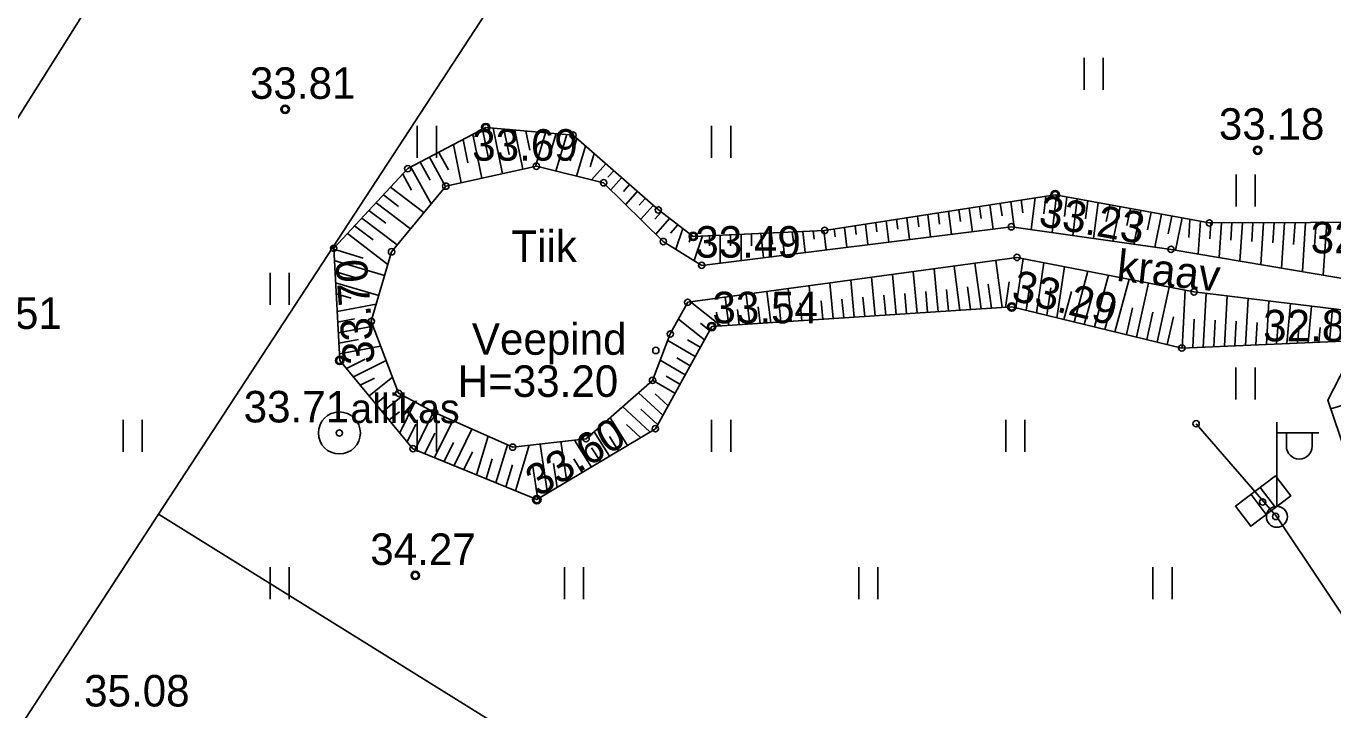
# Model space of a CAD drawing. Extents: x 641898 to 642452, y 6471715 to 6472255.
# Drawn here: x 641996.97 to 642028.05, y 6472175.9 to 6472192.17 of the extents above; entities that cross this region are included whole.
import ezdxf

# ---------------------------------------------------------------- set-up
doc = ezdxf.new("R2010")
doc.units = 0
for name, color, linetype in [('ELRAJATISMP', 7, 'Continuous'), ('HALJASTUS', 7, 'Continuous'), ('KORGUS-EH2000', 7, 'Continuous'), ('MOOTMPUNKT', 7, 'Continuous'), ('MOOTPIIR', 7, 'Continuous'), ('MPOHULIIN', 7, 'Continuous'), ('PIIR', 7, 'Continuous'), ('POST', 7, 'Continuous'), ('RELJEEF', 7, 'Continuous'), ('VEEKOGU', 7, 'Continuous')]:
    doc.layers.add(name, color=color, linetype=linetype)

msp = doc.modelspace()

# ---------------------------------------------------------------- linework, layer by layer
at = {"layer": 'ELRAJATISMP'}
for p, q in [((642026.323, 6472181.185), (642026.685, 6472180.711)), ((642026.107, 6472181.02), (642026.469, 6472180.546))]:
    msp.add_line(p, q, dxfattribs=at)
msp.add_lwpolyline([(642025.74, 6472180.741), (642026.69, 6472181.465), (642027.052, 6472180.99), (642026.102, 6472180.266)], close=True, dxfattribs=at)
at = {"layer": 'HALJASTUS'}
for p, q in [((642022.137, 6472191.415), (642022.137, 6472190.654)), ((642022.593, 6472191.415), (642022.593, 6472190.654)), ((642006.275, 6472189.795), (642006.275, 6472189.034)), ((642006.73, 6472189.795), (642006.73, 6472189.034)), ((642013.275, 6472189.795), (642013.275, 6472189.034)), ((642013.73, 6472189.795), (642013.73, 6472189.034)), ((642025.752, 6472188.637), (642025.752, 6472187.876)), ((642026.207, 6472188.637), (642026.207, 6472187.876)), ((642002.775, 6472186.295), (642002.775, 6472185.534)), ((642003.23, 6472186.295), (642003.23, 6472185.534)), ((642025.749, 6472184.045), (642025.749, 6472183.283)), ((642026.204, 6472184.045), (642026.204, 6472183.283)), ((641999.275, 6472182.795), (641999.275, 6472182.034)), ((641999.73, 6472182.795), (641999.73, 6472182.034)), ((642006.275, 6472182.795), (642006.275, 6472182.034)), ((642006.73, 6472182.795), (642006.73, 6472182.034)), ((642013.275, 6472182.795), (642013.275, 6472182.034)), ((642013.73, 6472182.795), (642013.73, 6472182.034)), ((642020.275, 6472182.795), (642020.275, 6472182.034)), ((642020.73, 6472182.795), (642020.73, 6472182.034)), ((642002.775, 6472179.295), (642002.775, 6472178.534)), ((642003.23, 6472179.295), (642003.23, 6472178.534)), ((642009.775, 6472179.295), (642009.775, 6472178.534)), ((642010.23, 6472179.295), (642010.23, 6472178.534)), ((642016.775, 6472179.295), (642016.775, 6472178.534)), ((642017.23, 6472179.295), (642017.23, 6472178.534)), ((642023.775, 6472179.295), (642023.775, 6472178.534)), ((642024.23, 6472179.295), (642024.23, 6472178.534))]:
    msp.add_line(p, q, dxfattribs=at)
at = {"layer": 'KORGUS-EH2000'}
for centre in [(642003.132, 6472190.189), (642007.903, 6472189.755), (642026.265, 6472189.215), (642021.447, 6472188.157), (642012.84, 6472187.165), (642020.417, 6472185.485), (642013.278, 6472185.019), (642004.429, 6472184.212), (642009.118, 6472180.899), (642006.227, 6472179.095)]:
    msp.add_circle(centre, 0.1, dxfattribs=at)
at = {"layer": 'MOOTMPUNKT'}
for centre in [(642003.132, 6472190.189), (642007.903, 6472189.755), (642009.98, 6472189.575), (642026.265, 6472189.215), (642009.107, 6472188.835), (642006.049, 6472188.777), (642006.952, 6472188.36), (642010.706, 6472188.441), (642021.447, 6472188.157), (642012.009, 6472187.794), (642015.964, 6472187.306), (642020.406, 6472187.393), (642025.116, 6472187.485), (642012.126, 6472187.042), (642012.84, 6472187.165), (642004.286, 6472186.881), (642005.662, 6472186.798), (642020.539, 6472186.664), (642024.204, 6472186.855), (642013.04, 6472186.476), (642024.749, 6472185.844), (642012.708, 6472185.596), (642020.417, 6472185.485), (642005.18, 6472185.144), (642012.292, 6472184.843), (642013.278, 6472185.019), (642024.46, 6472184.508), (642004.429, 6472184.212), (642011.949, 6472184.45), (642011.87, 6472183.737), (642005.83, 6472183.431), (642006.686, 6472182.974), (642024.801, 6472182.707), (642004.421, 6472182.487), (642010.29, 6472182.35), (642011.938, 6472182.588), (642006.172, 6472182.112), (642008.545, 6472182.148), (642009.118, 6472180.899), (642026.384, 6472180.843), (642026.694, 6472180.499), (642006.227, 6472179.095)]:
    msp.add_circle(centre, 0.075, dxfattribs=at)
at = {"layer": 'MOOTPIIR'}
msp.add_lwpolyline([(642014.306, 6472085.384), (642027.67, 6472104.979), (642055.501, 6472084.843), (642081.563, 6472094.262), (642123.938, 6472142.273), (642065.721, 6472244.475), (642008.922, 6472196.948), (642003.347, 6472200.453), (641979.65, 6472162.756), (641979.65, 6472162.756), (641986.045, 6472158.736), (642004.269, 6472142.365), (641987.048, 6472123.488), (641970.482, 6472097.889), (641986.758, 6472084.396)], close=True, dxfattribs=at)
at = {"layer": 'MPOHULIIN'}
msp.add_lwpolyline([(642026.721, 6472180.493), (642057.005, 6472135.15), (642092.759, 6472082.232), (642082.032, 6472055.789), (642066.817, 6472023.473)], dxfattribs=at)
at = {"layer": 'PIIR'}
for p, q in [((642031.85, 6472229.19), (642000.12, 6472180.55)), ((642000.12, 6472180.55), (641967.79, 6472130.98)), ((642000.12, 6472180.55), (642028, 6472163.22))]:
    msp.add_line(p, q, dxfattribs=at)
at = {"layer": 'POST'}
for p, q in [((642024.801, 6472182.707), (642026.721, 6472180.493)), ((642026.721, 6472180.743), (642026.721, 6472182.743)), ((642026.721, 6472182.493), (642027.721, 6472182.493)), ((642026.948, 6472182.172), (642026.948, 6472182.493)), ((642027.56, 6472182.172), (642027.56, 6472182.493)), ((642026.721, 6472180.493), (642026.721, 6472180.493))]:
    msp.add_line(p, q, dxfattribs=at)
msp.add_circle((642026.721, 6472180.493), 0.25, dxfattribs=at)
msp.add_arc((642027.254, 6472182.172), 0.306, 180, 0, dxfattribs=at)
at = {"layer": 'RELJEEF'}
for p, q in [((642007.597, 6472189.593), (642007.809, 6472188.549)), ((642007.827, 6472189.715), (642007.969, 6472189.017)), ((642008.077, 6472189.74), (642008.298, 6472188.657)), ((642008.337, 6472189.717), (642008.459, 6472189.117)), ((642008.596, 6472189.695), (642008.786, 6472188.764)), ((642008.856, 6472189.672), (642008.949, 6472189.216)), ((642009.325, 6472189.632), (642009.084, 6472188.83)), ((642009.58, 6472189.61), (642009.43, 6472189.111)), ((642009.834, 6472189.588), (642009.573, 6472188.72)), ((642007.136, 6472189.35), (642007.321, 6472188.441)), ((642007.366, 6472189.472), (642007.479, 6472188.917)), ((642010.068, 6472189.498), (642009.908, 6472188.967)), ((642010.275, 6472189.316), (642010.059, 6472188.6)), ((642006.342, 6472188.931), (642006.578, 6472188.505)), ((642006.563, 6472189.048), (642006.947, 6472188.354)), ((642006.784, 6472189.165), (642007.015, 6472188.747)), ((642010.481, 6472189.135), (642010.387, 6472188.823)), ((642005.928, 6472188.647), (642006.14, 6472188.262)), ((642006.12, 6472188.815), (642006.605, 6472187.94)), ((642010.758, 6472188.892), (642010.416, 6472188.513)), ((642010.946, 6472188.727), (642010.806, 6472188.572)), ((642005.638, 6472188.335), (642006.433, 6472187.731)), ((642011.134, 6472188.562), (642010.875, 6472188.275)), ((642011.321, 6472188.397), (642011.177, 6472188.237)), ((642005.296, 6472187.967), (642006.114, 6472187.346)), ((642005.467, 6472188.151), (642005.826, 6472187.878)), ((642011.508, 6472188.234), (642011.233, 6472187.922)), ((642011.696, 6472188.069), (642011.552, 6472187.906)), ((642020.39, 6472187.993), (642020.473, 6472187.384)), ((642020.637, 6472188.031), (642020.679, 6472187.722)), ((642020.97, 6472188.083), (642020.877, 6472187.326)), ((642021.226, 6472188.123), (642021.175, 6472187.703)), ((642021.482, 6472188.151), (642021.373, 6472187.256)), ((642021.728, 6472188.106), (642021.672, 6472187.642)), ((642021.974, 6472188.06), (642021.868, 6472187.186)), ((642022.221, 6472188.015), (642022.168, 6472187.582)), ((642022.467, 6472187.97), (642022.363, 6472187.116)), ((642005.125, 6472187.783), (642005.524, 6472187.48)), ((642011.884, 6472187.904), (642011.589, 6472187.571)), ((642012.076, 6472187.744), (642011.926, 6472187.575)), ((642018.417, 6472187.687), (642018.482, 6472187.153)), ((642018.664, 6472187.725), (642018.697, 6472187.454)), ((642018.908, 6472187.763), (642018.982, 6472187.216)), ((642019.155, 6472187.801), (642019.193, 6472187.52)), ((642019.402, 6472187.84), (642019.478, 6472187.277)), ((642019.649, 6472187.878), (642019.688, 6472187.587)), ((642019.896, 6472187.916), (642019.974, 6472187.339)), ((642020.143, 6472187.955), (642020.184, 6472187.655)), ((642022.745, 6472187.919), (642022.664, 6472187.521)), ((642022.991, 6472187.874), (642022.823, 6472187.051)), ((642023.237, 6472187.829), (642023.154, 6472187.421)), ((642023.483, 6472187.784), (642023.319, 6472186.98)), ((642023.729, 6472187.739), (642023.644, 6472187.321)), ((642023.975, 6472187.694), (642023.815, 6472186.91)), ((642004.782, 6472187.415), (642005.221, 6472187.082)), ((642004.953, 6472187.599), (642005.796, 6472186.96)), ((642012.275, 6472187.592), (642011.946, 6472187.219)), ((642012.475, 6472187.441), (642012.301, 6472187.244)), ((642012.589, 6472187.355), (642012.421, 6472186.86)), ((642016.193, 6472187.342), (642016.215, 6472187.153)), ((642016.44, 6472187.38), (642016.496, 6472186.906)), ((642016.687, 6472187.418), (642016.712, 6472187.212)), ((642016.934, 6472187.457), (642016.994, 6472186.968)), ((642017.181, 6472187.495), (642017.208, 6472187.272)), ((642017.428, 6472187.533), (642017.49, 6472187.03)), ((642017.675, 6472187.572), (642017.705, 6472187.333)), ((642017.923, 6472187.61), (642017.986, 6472187.092)), ((642018.17, 6472187.648), (642018.201, 6472187.394)), ((642024.221, 6472187.649), (642024.134, 6472187.222)), ((642024.467, 6472187.604), (642024.311, 6472186.837)), ((642024.655, 6472187.569), (642024.626, 6472187.14)), ((642024.902, 6472187.524), (642024.851, 6472186.746)), ((642025.15, 6472187.485), (642025.125, 6472187.107)), ((642025.401, 6472187.486), (642025.346, 6472186.662)), ((642025.652, 6472187.487), (642025.624, 6472187.074)), ((642025.902, 6472187.488), (642025.842, 6472186.578)), ((642026.153, 6472187.489), (642026.123, 6472187.041)), ((642026.403, 6472187.49), (642026.337, 6472186.495)), ((642026.654, 6472187.492), (642026.622, 6472187.008)), ((642026.905, 6472187.493), (642026.833, 6472186.411)), ((642027.156, 6472187.494), (642027.121, 6472186.974)), ((642027.406, 6472187.495), (642027.328, 6472186.327)), ((642027.657, 6472187.496), (642027.62, 6472186.941)), ((642027.907, 6472187.497), (642027.824, 6472186.244)), ((642004.611, 6472187.231), (642005.575, 6472186.499)), ((642012.799, 6472187.196), (642012.741, 6472187.026)), ((642013.056, 6472187.175), (642012.857, 6472186.589)), ((642013.228, 6472187.182), (642013.228, 6472186.942)), ((642013.478, 6472187.194), (642013.478, 6472186.53)), ((642013.728, 6472187.205), (642013.728, 6472186.942)), ((642013.978, 6472187.216), (642013.978, 6472186.593)), ((642014.228, 6472187.228), (642014.228, 6472186.942)), ((642014.444, 6472187.237), (642014.511, 6472186.659)), ((642014.694, 6472187.249), (642014.726, 6472186.978)), ((642014.944, 6472187.26), (642015.007, 6472186.721)), ((642015.195, 6472187.271), (642015.222, 6472187.037)), ((642015.445, 6472187.283), (642015.504, 6472186.783)), ((642015.695, 6472187.294), (642015.719, 6472187.095)), ((642015.946, 6472187.305), (642016, 6472186.844)), ((642004.287, 6472186.858), (642004.987, 6472186.649)), ((642004.301, 6472186.593), (642005.498, 6472186.236)), ((642019.184, 6472185.405), (642019.044, 6472186.46)), ((642019.684, 6472185.437), (642019.539, 6472186.528)), ((642020.184, 6472185.47), (642020.035, 6472186.595)), ((642020.514, 6472185.462), (642020.688, 6472186.635)), ((642021.002, 6472185.344), (642021.179, 6472186.539)), ((642021.49, 6472185.226), (642021.671, 6472186.444)), ((642004.316, 6472186.327), (642004.844, 6472186.17)), ((642016.667, 6472185.24), (642016.587, 6472186.125)), ((642017.166, 6472185.273), (642017.082, 6472186.193)), ((642017.665, 6472185.305), (642017.578, 6472186.26)), ((642018.165, 6472185.338), (642018.074, 6472186.328)), ((642018.664, 6472185.371), (642018.57, 6472186.395)), ((642021.897, 6472185.127), (642022.226, 6472186.335)), ((642022.383, 6472185.01), (642022.718, 6472186.24)), ((642022.869, 6472184.892), (642023.21, 6472186.144)), ((642004.33, 6472186.062), (642005.358, 6472185.756)), ((642004.344, 6472185.797), (642004.701, 6472185.691)), ((642014.683, 6472185.111), (642014.592, 6472185.853)), ((642015.169, 6472185.142), (642015.099, 6472185.922)), ((642015.668, 6472185.175), (642015.595, 6472185.99)), ((642016.168, 6472185.208), (642016.091, 6472186.057)), ((642017.915, 6472185.322), (642017.87, 6472185.809)), ((642018.414, 6472185.354), (642018.368, 6472185.855)), ((642018.913, 6472185.387), (642018.866, 6472185.9)), ((642019.434, 6472185.421), (642019.362, 6472185.961)), ((642019.934, 6472185.453), (642019.858, 6472186.027)), ((642020.263, 6472185.475), (642020.354, 6472186.084)), ((642020.758, 6472185.403), (642020.848, 6472186.01)), ((642021.246, 6472185.285), (642021.343, 6472185.937)), ((642021.653, 6472185.186), (642021.835, 6472185.851)), ((642023.386, 6472184.768), (642023.671, 6472186.054)), ((642023.872, 6472184.65), (642024.162, 6472185.958)), ((642024.469, 6472184.508), (642024.544, 6472185.884)), ((642024.971, 6472184.53), (642025.04, 6472185.809)), ((642004.367, 6472185.376), (642005.3, 6472185.554)), ((642013.498, 6472185.033), (642012.772, 6472185.605)), ((642013.684, 6472185.045), (642013.602, 6472185.718)), ((642014.184, 6472185.078), (642014.097, 6472185.785)), ((642014.433, 6472185.094), (642014.386, 6472185.485)), ((642014.92, 6472185.126), (642014.883, 6472185.539)), ((642015.419, 6472185.159), (642015.381, 6472185.584)), ((642015.918, 6472185.191), (642015.879, 6472185.629)), ((642016.417, 6472185.224), (642016.377, 6472185.673)), ((642016.917, 6472185.257), (642016.875, 6472185.718)), ((642017.416, 6472185.289), (642017.372, 6472185.764)), ((642022.14, 6472185.069), (642022.317, 6472185.72)), ((642022.626, 6472184.951), (642022.8, 6472185.588)), ((642025.473, 6472184.551), (642025.538, 6472185.749)), ((642025.974, 6472184.572), (642026.035, 6472185.688)), ((642026.476, 6472184.593), (642026.533, 6472185.628)), ((642026.962, 6472184.614), (642027.047, 6472185.566)), ((642027.466, 6472184.635), (642027.544, 6472185.506)), ((642004.38, 6472185.124), (642004.781, 6472185.2)), ((642013.105, 6472184.706), (642012.486, 6472185.193)), ((642013.434, 6472185.029), (642013.393, 6472185.364)), ((642013.934, 6472185.062), (642013.889, 6472185.425)), ((642023.143, 6472184.826), (642023.284, 6472185.467)), ((642023.629, 6472184.709), (642023.773, 6472185.359)), ((642024.115, 6472184.591), (642024.261, 6472185.251)), ((642024.72, 6472184.519), (642024.757, 6472185.198)), ((642025.222, 6472184.54), (642025.256, 6472185.171)), ((642027.97, 6472184.657), (642028.041, 6472185.446)), ((642004.394, 6472184.872), (642005.223, 6472185.031)), ((642013.228, 6472184.928), (642013.013, 6472185.097)), ((642025.724, 6472184.562), (642025.755, 6472185.144)), ((642026.225, 6472184.583), (642026.254, 6472185.117)), ((642026.71, 6472184.603), (642026.754, 6472185.089)), ((642027.214, 6472184.625), (642027.252, 6472185.044)), ((642027.718, 6472184.646), (642027.75, 6472184.999)), ((642004.407, 6472184.62), (642004.874, 6472184.709)), ((642004.421, 6472184.368), (642005.403, 6472184.556)), ((642012.886, 6472184.307), (642012.234, 6472184.69)), ((642013.006, 6472184.526), (642012.704, 6472184.704)), ((642004.591, 6472184.017), (642005.033, 6472184.24)), ((642012.765, 6472184.088), (642012.451, 6472184.272)), ((642004.755, 6472183.82), (642005.533, 6472184.213)), ((642012.644, 6472183.869), (642012.053, 6472184.216)), ((642031.565, 6472184.12), (642028.001, 6472183.062)), ((642004.918, 6472183.622), (642005.259, 6472183.794)), ((642005.126, 6472183.373), (642005.683, 6472183.818)), ((642012.403, 6472183.431), (642011.872, 6472183.743)), ((642012.523, 6472183.65), (642012.198, 6472183.841)), ((642005.285, 6472183.18), (642005.539, 6472183.383)), ((642005.445, 6472182.988), (642005.932, 6472183.377)), ((642012.115, 6472182.91), (642011.536, 6472183.444)), ((642012.24, 6472183.135), (642011.932, 6472183.42)), ((642005.605, 6472182.795), (642005.851, 6472182.993)), ((642005.859, 6472182.489), (642006.22, 6472183.223)), ((642011.81, 6472182.511), (642011.159, 6472183.113)), ((642011.991, 6472182.684), (642011.592, 6472183.052)), ((642006.034, 6472182.278), (642006.242, 6472182.699)), ((642006.221, 6472182.092), (642006.662, 6472182.987)), ((642006.685, 6472181.901), (642007.118, 6472182.782)), ((642011.273, 6472182.19), (642010.859, 6472182.849)), ((642011.586, 6472182.377), (642011.253, 6472182.685)), ((642006.453, 6472181.996), (642006.69, 6472182.479)), ((642007.148, 6472181.71), (642007.575, 6472182.579)), ((642007.681, 6472181.491), (642007.959, 6472182.408)), ((642010.844, 6472181.933), (642010.478, 6472182.515)), ((642011.058, 6472182.061), (642010.846, 6472182.4)), ((642006.917, 6472181.805), (642007.139, 6472182.258)), ((642008.145, 6472181.299), (642008.42, 6472182.204)), ((642008.61, 6472181.108), (642008.939, 6472182.194)), ((642009.371, 6472181.05), (642009.194, 6472182.223)), ((642009.835, 6472181.328), (642009.691, 6472182.281)), ((642010.415, 6472181.676), (642010.012, 6472182.318)), ((642010.629, 6472181.804), (642010.422, 6472182.134)), ((642007.38, 6472181.615), (642007.588, 6472182.037)), ((642007.913, 6472181.395), (642008.057, 6472181.87)), ((642009.603, 6472181.189), (642009.516, 6472181.761)), ((642010.2, 6472181.547), (642009.999, 6472181.869)), ((642008.378, 6472181.204), (642008.536, 6472181.725)), ((642009.139, 6472180.912), (642009.022, 6472181.686))]:
    msp.add_line(p, q, dxfattribs=at)
msp.add_lwpolyline([(642034.946, 6472175.537), (642029.211, 6472179.503), (642027.931, 6472183.268), (642028.661, 6472184.686), (642024.46, 6472184.508), (642020.417, 6472185.485), (642013.278, 6472185.019), (642011.938, 6472182.588), (642009.118, 6472180.899), (642006.172, 6472182.112), (642004.429, 6472184.212), (642004.286, 6472186.881), (642006.049, 6472188.777), (642007.903, 6472189.755), (642009.98, 6472189.575), (642012.009, 6472187.794), (642012.84, 6472187.165), (642015.964, 6472187.306), (642021.447, 6472188.157), (642025.116, 6472187.485), (642029.934, 6472187.506), (642033.4, 6472192.669)], dxfattribs=at)
at = {"layer": 'VEEKOGU'}
msp.add_lwpolyline([(642029.509, 6472185.268), (642024.749, 6472185.844), (642020.539, 6472186.664), (642012.708, 6472185.596), (642012.292, 6472184.843), (642011.87, 6472183.737), (642010.29, 6472182.35), (642008.545, 6472182.148), (642006.686, 6472182.974), (642005.83, 6472183.431), (642005.18, 6472185.144), (642005.662, 6472186.798), (642006.952, 6472188.36), (642009.107, 6472188.835), (642010.706, 6472188.441), (642012.126, 6472187.042), (642013.04, 6472186.476), (642020.406, 6472187.393), (642024.204, 6472186.855), (642029.32, 6472185.991)], dxfattribs=at)
msp.add_circle((642004.421, 6472182.487), 0.5, dxfattribs=at)

# ---------------------------------------------------------------- texts
at = {"layer": 'KORGUS-EH2000'}
for s, p in [('33.81', (642002.295, 6472190.439)), ('33.18', (642025.342, 6472189.465)), ('33.69', (642007.581, 6472188.967)), ('33.49', (642012.888, 6472186.659)), ('32.93', (642027.526, 6472186.762)), ('33.54', (642013.295, 6472185.097)), ('34.51', (641995.31, 6472184.963)), ('32.88', (642026.396, 6472184.667)), ('Veepind', (642007.572, 6472184.348)), ('H=33.20', (642007.235, 6472183.345)), ('33.71', (642002.144, 6472182.737)), ('34.27', (642005.156, 6472179.345)), ('35.08', (641998.349, 6472175.976))]:
    msp.add_text(s, height=0.75, dxfattribs=at).set_placement(p)
for s, rotation, p in [('33.23', 349.9898, (642021.03, 6472187.419)), ('33.70', 94.3529, (642005.263, 6472184.148)), ('33.29', 345.774, (642020.375, 6472185.654)), ('33.60', 31.2763, (642009.152, 6472180.948))]:
    msp.add_text(s, height=0.75, rotation=rotation, dxfattribs=at).set_placement(p)
at = {"layer": 'VEEKOGU'}
for s, height, p in [('Tiik', 0.75, (642008.51, 6472186.557)), (' allikas', 0.7, (642004.421, 6472182.72))]:
    msp.add_text(s, height=height, dxfattribs=at).set_placement(p)
msp.add_text('kraav', height=0.75, rotation=353.9667, dxfattribs=at).set_placement((642022.891, 6472186.108))

doc.saveas('drawing.dxf')
